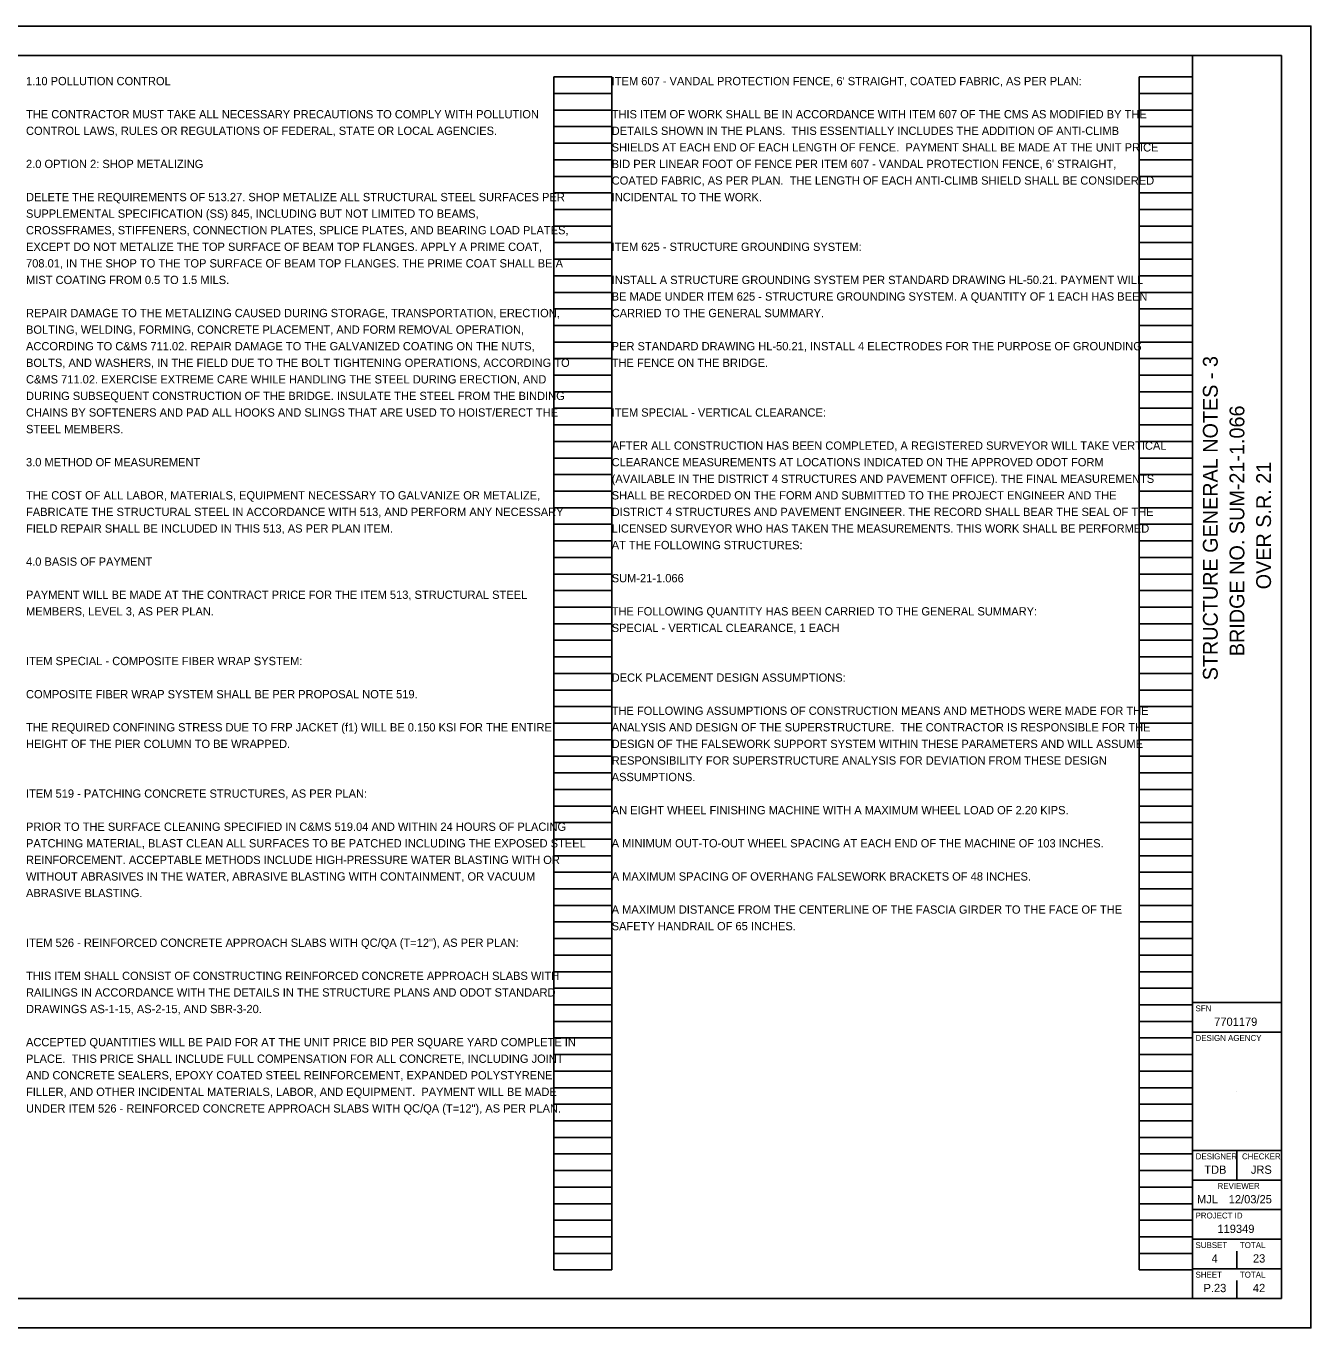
# Model space of a CAD drawing. Extents: x 0 to 34, y 0 to 22.
# Drawn here: x 12.29 to 34, y 0 to 22 of the extents above; entities that cross this region are included whole.
import ezdxf

# ---------------------------------------------------------------- set-up
doc = ezdxf.new("R2010")
doc.units = 0
for name, color, linetype in [('SH_Border', 7, 'Continuous'), ('SH_Cut_Line', 7, 'Continuous'), ('SH_Data', 7, 'Continuous'), ('SH_Text', 7, 'Continuous')]:
    doc.layers.add(name, color=color, linetype=linetype)

msp = doc.modelspace()

# ---------------------------------------------------------------- linework, layer by layer
at = {"layer": 'SH_Border'}
for p, q in [((32, 0.5), (32, 21.5)), ((32, 5.5), (33.5, 5.5)), ((32, 5), (33.5, 5)), ((32, 3), (33.5, 3)), ((32.75, 3), (32.75, 2.5)), ((32, 2.5), (33.5, 2.5)), ((32, 2), (33.5, 2)), ((32, 1.5), (33.5, 1.5)), ((32, 1), (33.5, 1))]:
    msp.add_line(p, q, dxfattribs=at)
msp.add_lwpolyline([(1.5, 21.5), (33.5, 21.5), (33.5, 0.5), (1.5, 0.5)], close=True, dxfattribs=at)
at = {"layer": 'SH_Cut_Line'}
msp.add_lwpolyline([(0, 0), (34, 0), (34, 22), (0, 22)], close=True, dxfattribs=at)
at = {"layer": 'SH_Data'}
for p, q in [((21.207, 0.98), (21.207, 21.14)), ((21.207, 21.14), (22.187, 21.14)), ((22.187, 0.98), (22.187, 21.14)), ((31.1, 0.98), (31.1, 21.14)), ((31.1, 21.14), (32, 21.14)), ((32, 0.98), (32, 21.14)), ((21.207, 20.86), (22.187, 20.86)), ((31.1, 20.86), (32, 20.86)), ((21.207, 20.58), (22.187, 20.58)), ((31.1, 20.58), (32, 20.58)), ((21.207, 20.3), (22.187, 20.3)), ((31.1, 20.3), (32, 20.3)), ((21.207, 20.02), (22.187, 20.02)), ((31.1, 20.02), (32, 20.02)), ((21.207, 19.74), (22.187, 19.74)), ((31.1, 19.74), (32, 19.74)), ((21.207, 19.46), (22.187, 19.46)), ((31.1, 19.46), (32, 19.46)), ((21.207, 19.18), (22.187, 19.18)), ((31.1, 19.18), (32, 19.18)), ((21.207, 18.9), (22.187, 18.9)), ((31.1, 18.9), (32, 18.9)), ((21.207, 18.62), (22.187, 18.62)), ((31.1, 18.62), (32, 18.62)), ((21.207, 18.34), (22.187, 18.34)), ((31.1, 18.34), (32, 18.34)), ((21.207, 18.06), (22.187, 18.06)), ((31.1, 18.06), (32, 18.06)), ((21.207, 17.78), (22.187, 17.78)), ((31.1, 17.78), (32, 17.78)), ((21.207, 17.5), (22.187, 17.5)), ((31.1, 17.5), (32, 17.5)), ((21.207, 17.22), (22.187, 17.22)), ((31.1, 17.22), (32, 17.22)), ((21.207, 16.94), (22.187, 16.94)), ((31.1, 16.94), (32, 16.94)), ((21.207, 16.66), (22.187, 16.66)), ((31.1, 16.66), (32, 16.66)), ((21.207, 16.38), (22.187, 16.38)), ((31.1, 16.38), (32, 16.38)), ((21.207, 16.1), (22.187, 16.1)), ((31.1, 16.1), (32, 16.1)), ((21.207, 15.82), (22.187, 15.82)), ((31.1, 15.82), (32, 15.82)), ((21.207, 15.54), (22.187, 15.54)), ((31.1, 15.54), (32, 15.54)), ((21.207, 15.26), (22.187, 15.26)), ((31.1, 15.26), (32, 15.26)), ((21.207, 14.98), (22.187, 14.98)), ((31.1, 14.98), (32, 14.98)), ((21.207, 14.7), (22.187, 14.7)), ((31.1, 14.7), (32, 14.7)), ((21.207, 14.42), (22.187, 14.42)), ((31.1, 14.42), (32, 14.42)), ((21.207, 14.14), (22.187, 14.14)), ((31.1, 14.14), (32, 14.14)), ((21.207, 13.86), (22.187, 13.86)), ((31.1, 13.86), (32, 13.86)), ((21.207, 13.58), (22.187, 13.58)), ((31.1, 13.58), (32, 13.58)), ((21.207, 13.3), (22.187, 13.3)), ((31.1, 13.3), (32, 13.3)), ((21.207, 13.02), (22.187, 13.02)), ((31.1, 13.02), (32, 13.02)), ((21.207, 12.74), (22.187, 12.74)), ((31.1, 12.74), (32, 12.74)), ((21.207, 12.46), (22.187, 12.46)), ((31.1, 12.46), (32, 12.46)), ((21.207, 12.18), (22.187, 12.18)), ((31.1, 12.18), (32, 12.18)), ((21.207, 11.9), (22.187, 11.9)), ((31.1, 11.9), (32, 11.9)), ((21.207, 11.62), (22.187, 11.62)), ((31.1, 11.62), (32, 11.62)), ((21.207, 11.34), (22.187, 11.34)), ((31.1, 11.34), (32, 11.34)), ((21.207, 11.06), (22.187, 11.06)), ((31.1, 11.06), (32, 11.06)), ((21.207, 10.78), (22.187, 10.78)), ((31.1, 10.78), (32, 10.78)), ((21.207, 10.5), (22.187, 10.5)), ((31.1, 10.5), (32, 10.5)), ((21.207, 10.22), (22.187, 10.22)), ((31.1, 10.22), (32, 10.22)), ((21.207, 9.94), (22.187, 9.94)), ((31.1, 9.94), (32, 9.94)), ((21.207, 9.66), (22.187, 9.66)), ((31.1, 9.66), (32, 9.66)), ((21.207, 9.38), (22.187, 9.38)), ((31.1, 9.38), (32, 9.38)), ((21.207, 9.1), (22.187, 9.1)), ((31.1, 9.1), (32, 9.1)), ((21.207, 8.82), (22.187, 8.82)), ((31.1, 8.82), (32, 8.82)), ((21.207, 8.54), (22.187, 8.54)), ((31.1, 8.54), (32, 8.54)), ((21.207, 8.26), (22.187, 8.26)), ((31.1, 8.26), (32, 8.26)), ((21.207, 7.98), (22.187, 7.98)), ((31.1, 7.98), (32, 7.98)), ((21.207, 7.7), (22.187, 7.7)), ((31.1, 7.7), (32, 7.7)), ((21.207, 7.42), (22.187, 7.42)), ((31.1, 7.42), (32, 7.42)), ((21.207, 7.14), (22.187, 7.14)), ((31.1, 7.14), (32, 7.14)), ((21.207, 6.86), (22.187, 6.86)), ((31.1, 6.86), (32, 6.86)), ((21.207, 6.58), (22.187, 6.58)), ((31.1, 6.58), (32, 6.58)), ((21.207, 6.3), (22.187, 6.3)), ((31.1, 6.3), (32, 6.3)), ((21.207, 6.02), (22.187, 6.02)), ((31.1, 6.02), (32, 6.02)), ((21.207, 5.74), (22.187, 5.74)), ((31.1, 5.74), (32, 5.74)), ((21.207, 5.46), (22.187, 5.46)), ((31.1, 5.46), (32, 5.46)), ((21.207, 5.18), (22.187, 5.18)), ((31.1, 5.18), (32, 5.18)), ((21.207, 4.9), (22.187, 4.9)), ((31.1, 4.9), (32, 4.9)), ((21.207, 4.62), (22.187, 4.62)), ((31.1, 4.62), (32, 4.62)), ((21.207, 4.34), (22.187, 4.34)), ((31.1, 4.34), (32, 4.34)), ((21.207, 4.06), (22.187, 4.06)), ((31.1, 4.06), (32, 4.06)), ((32.75, 4), (32.75, 4)), ((21.207, 3.78), (22.187, 3.78)), ((31.1, 3.78), (32, 3.78)), ((21.207, 3.5), (22.187, 3.5)), ((31.1, 3.5), (32, 3.5)), ((21.207, 3.22), (22.187, 3.22)), ((31.1, 3.22), (32, 3.22)), ((21.207, 2.94), (22.187, 2.94)), ((31.1, 2.94), (32, 2.94)), ((21.207, 2.66), (22.187, 2.66)), ((31.1, 2.66), (32, 2.66)), ((21.207, 2.38), (22.187, 2.38)), ((31.1, 2.38), (32, 2.38)), ((21.207, 2.1), (22.187, 2.1)), ((31.1, 2.1), (32, 2.1)), ((21.207, 1.82), (22.187, 1.82)), ((31.1, 1.82), (32, 1.82)), ((21.207, 1.54), (22.187, 1.54)), ((31.1, 1.54), (32, 1.54)), ((21.207, 1.26), (22.187, 1.26)), ((31.1, 1.26), (32, 1.26)), ((32.75, 1), (32.75, 1.3)), ((21.207, 0.98), (22.187, 0.98)), ((31.1, 0.98), (32, 0.98)), ((32.375, 0.675), (32.375, 0.675)), ((32.75, 0.5), (32.75, 0.8))]:
    msp.add_line(p, q, dxfattribs=at)

# ---------------------------------------------------------------- texts
for s, p in [('STRUCTURE GENERAL NOTES - 3', (32.425, 10.944)), ('BRIDGE NO. SUM-21-1.066', (32.875, 11.352)), ('OVER S.R. 21', (33.325, 12.482))]:
    msp.add_text(s, height=0.25, rotation=90, dxfattribs=at).set_placement(p)
for s, height, p in [('SFN', 0.1, (32.05, 5.35)), ('7701179', 0.14, (32.365, 5.105)), ('DESIGN AGENCY', 0.1, (32.05, 4.85)), ('DESIGNER', 0.1, (32.054, 2.85)), ('CHECKER', 0.1, (32.835, 2.85)), ('TDB', 0.14, (32.198, 2.605)), ('JRS', 0.14, (32.985, 2.605)), ('REVIEWER', 0.1, (32.422, 2.35)), ('MJL', 0.14, (32.075, 2.105)), ('12/03/25', 0.14, (32.611, 2.105)), ('PROJECT ID', 0.1, (32.05, 1.85)), ('119349', 0.14, (32.42, 1.605)), ('SUBSET', 0.1, (32.05, 1.35)), ('TOTAL', 0.1, (32.8, 1.35)), ('4', 0.14, (32.322, 1.105)), ('23', 0.14, (33.02, 1.105)), ('SHEET', 0.1, (32.05, 0.85)), ('TOTAL', 0.1, (32.8, 0.85)), ('P.23', 0.14, (32.185, 0.605)), ('42', 0.14, (33.019, 0.605))]:
    msp.add_text(s, height=height, dxfattribs=at).set_placement(p)
at = {"layer": 'SH_Text'}
for s, p in [('1.10 POLLUTION CONTROL', (12.293, 21)), ("ITEM 607 - VANDAL PROTECTION FENCE, 6' STRAIGHT, COATED FABRIC, AS PER PLAN:", (22.187, 21)), ('THE CONTRACTOR MUST TAKE ALL NECESSARY PRECAUTIONS TO COMPLY WITH POLLUTION ', (12.293, 20.44)), ('THIS ITEM OF WORK SHALL BE IN ACCORDANCE WITH ITEM 607 OF THE CMS AS MODIFIED BY THE ', (22.187, 20.44)), ('CONTROL LAWS, RULES OR REGULATIONS OF FEDERAL, STATE OR LOCAL AGENCIES.', (12.293, 20.16)), ('DETAILS SHOWN IN THE PLANS.  THIS ESSENTIALLY INCLUDES THE ADDITION OF ANTI-CLIMB ', (22.187, 20.16)), ('SHIELDS AT EACH END OF EACH LENGTH OF FENCE.  PAYMENT SHALL BE MADE AT THE UNIT PRICE ', (22.187, 19.88)), ('2.0 OPTION 2: SHOP METALIZING', (12.293, 19.6)), ("BID PER LINEAR FOOT OF FENCE PER ITEM 607 - VANDAL PROTECTION FENCE, 6' STRAIGHT, ", (22.187, 19.6)), ('COATED FABRIC, AS PER PLAN.  THE LENGTH OF EACH ANTI-CLIMB SHIELD SHALL BE CONSIDERED ', (22.187, 19.32)), ('DELETE THE REQUIREMENTS OF 513.27. SHOP METALIZE ALL STRUCTURAL STEEL SURFACES PER ', (12.293, 19.04)), ('INCIDENTAL TO THE WORK.', (22.187, 19.04)), ('SUPPLEMENTAL SPECIFICATION (SS) 845, INCLUDING BUT NOT LIMITED TO BEAMS,', (12.293, 18.76)), ('CROSSFRAMES, STIFFENERS, CONNECTION PLATES, SPLICE PLATES, AND BEARING LOAD PLATES, ', (12.293, 18.48)), ('EXCEPT DO NOT METALIZE THE TOP SURFACE OF BEAM TOP FLANGES. APPLY A PRIME COAT, ', (12.293, 18.2)), ('ITEM 625 - STRUCTURE GROUNDING SYSTEM:', (22.187, 18.2)), ('708.01, IN THE SHOP TO THE TOP SURFACE OF BEAM TOP FLANGES. THE PRIME COAT SHALL BE A ', (12.293, 17.92)), ('MIST COATING FROM 0.5 TO 1.5 MILS.', (12.293, 17.64)), ('INSTALL A STRUCTURE GROUNDING SYSTEM PER STANDARD DRAWING HL-50.21. PAYMENT WILL ', (22.187, 17.64)), ('BE MADE UNDER ITEM 625 - STRUCTURE GROUNDING SYSTEM. A QUANTITY OF 1 EACH HAS BEEN ', (22.187, 17.36)), ('REPAIR DAMAGE TO THE METALIZING CAUSED DURING STORAGE, TRANSPORTATION, ERECTION, ', (12.293, 17.08)), ('CARRIED TO THE GENERAL SUMMARY.', (22.187, 17.08)), ('BOLTING, WELDING, FORMING, CONCRETE PLACEMENT, AND FORM REMOVAL OPERATION, ', (12.293, 16.8)), ('ACCORDING TO C&MS 711.02. REPAIR DAMAGE TO THE GALVANIZED COATING ON THE NUTS, ', (12.293, 16.52)), ('PER STANDARD DRAWING HL-50.21, INSTALL 4 ELECTRODES FOR THE PURPOSE OF GROUNDING ', (22.187, 16.52)), ('BOLTS, AND WASHERS, IN THE FIELD DUE TO THE BOLT TIGHTENING OPERATIONS, ACCORDING TO ', (12.293, 16.24)), ('THE FENCE ON THE BRIDGE.', (22.187, 16.24)), ('C&MS 711.02. EXERCISE EXTREME CARE WHILE HANDLING THE STEEL DURING ERECTION, AND ', (12.293, 15.96)), ('DURING SUBSEQUENT CONSTRUCTION OF THE BRIDGE. INSULATE THE STEEL FROM THE BINDING ', (12.293, 15.68)), ('CHAINS BY SOFTENERS AND PAD ALL HOOKS AND SLINGS THAT ARE USED TO HOIST/ERECT THE ', (12.293, 15.4)), ('ITEM SPECIAL - VERTICAL CLEARANCE:', (22.187, 15.4)), ('STEEL MEMBERS.', (12.293, 15.12)), ('AFTER ALL CONSTRUCTION HAS BEEN COMPLETED, A REGISTERED SURVEYOR WILL TAKE VERTICAL ', (22.187, 14.84)), ('3.0 METHOD OF MEASUREMENT', (12.293, 14.56)), ('CLEARANCE MEASUREMENTS AT LOCATIONS INDICATED ON THE APPROVED ODOT FORM ', (22.187, 14.56)), ('(AVAILABLE IN THE DISTRICT 4 STRUCTURES AND PAVEMENT OFFICE). THE FINAL MEASUREMENTS ', (22.187, 14.28)), ('THE COST OF ALL LABOR, MATERIALS, EQUIPMENT NECESSARY TO GALVANIZE OR METALIZE, ', (12.293, 14)), ('SHALL BE RECORDED ON THE FORM AND SUBMITTED TO THE PROJECT ENGINEER AND THE ', (22.187, 14)), ('FABRICATE THE STRUCTURAL STEEL IN ACCORDANCE WITH 513, AND PERFORM ANY NECESSARY ', (12.293, 13.72)), ('DISTRICT 4 STRUCTURES AND PAVEMENT ENGINEER. THE RECORD SHALL BEAR THE SEAL OF THE ', (22.187, 13.72)), ('FIELD REPAIR SHALL BE INCLUDED IN THIS 513, AS PER PLAN ITEM.', (12.293, 13.44)), ('LICENSED SURVEYOR WHO HAS TAKEN THE MEASUREMENTS. THIS WORK SHALL BE PERFORMED ', (22.187, 13.44)), ('AT THE FOLLOWING STRUCTURES: ', (22.187, 13.16)), ('4.0 BASIS OF PAYMENT', (12.293, 12.88)), ('SUM-21-1.066', (22.187, 12.6)), ('PAYMENT WILL BE MADE AT THE CONTRACT PRICE FOR THE ITEM 513, STRUCTURAL STEEL ', (12.293, 12.32)), ('MEMBERS, LEVEL 3, AS PER PLAN.', (12.293, 12.04)), ('THE FOLLOWING QUANTITY HAS BEEN CARRIED TO THE GENERAL SUMMARY: ', (22.187, 12.04)), ('SPECIAL - VERTICAL CLEARANCE, 1 EACH', (22.187, 11.76)), ('ITEM SPECIAL - COMPOSITE FIBER WRAP SYSTEM:', (12.293, 11.2)), ('DECK PLACEMENT DESIGN ASSUMPTIONS:', (22.187, 10.92)), ('COMPOSITE FIBER WRAP SYSTEM SHALL BE PER PROPOSAL NOTE 519.', (12.293, 10.64)), ('THE FOLLOWING ASSUMPTIONS OF CONSTRUCTION MEANS AND METHODS WERE MADE FOR THE ', (22.187, 10.36)), ('THE REQUIRED CONFINING STRESS DUE TO FRP JACKET (f1) WILL BE 0.150 KSI FOR THE ENTIRE ', (12.293, 10.08)), ('ANALYSIS AND DESIGN OF THE SUPERSTRUCTURE.  THE CONTRACTOR IS RESPONSIBLE FOR THE ', (22.187, 10.08)), ('HEIGHT OF THE PIER COLUMN TO BE WRAPPED.', (12.293, 9.8)), ('DESIGN OF THE FALSEWORK SUPPORT SYSTEM WITHIN THESE PARAMETERS AND WILL ASSUME ', (22.187, 9.8)), ('RESPONSIBILITY FOR SUPERSTRUCTURE ANALYSIS FOR DEVIATION FROM THESE DESIGN ', (22.187, 9.52)), ('ASSUMPTIONS.', (22.187, 9.24)), ('ITEM 519 - PATCHING CONCRETE STRUCTURES, AS PER PLAN:', (12.293, 8.96)), ('AN EIGHT WHEEL FINISHING MACHINE WITH A MAXIMUM WHEEL LOAD OF 2.20 KIPS.', (22.187, 8.68)), ('PRIOR TO THE SURFACE CLEANING SPECIFIED IN C&MS 519.04 AND WITHIN 24 HOURS OF PLACING ', (12.293, 8.4)), ('PATCHING MATERIAL, BLAST CLEAN ALL SURFACES TO BE PATCHED INCLUDING THE EXPOSED STEEL ', (12.293, 8.12)), ('A MINIMUM OUT-TO-OUT WHEEL SPACING AT EACH END OF THE MACHINE OF 103 INCHES.', (22.187, 8.12)), ('REINFORCEMENT. ACCEPTABLE METHODS INCLUDE HIGH-PRESSURE WATER BLASTING WITH OR ', (12.293, 7.84)), ('WITHOUT ABRASIVES IN THE WATER, ABRASIVE BLASTING WITH CONTAINMENT, OR VACUUM ', (12.293, 7.56)), ('A MAXIMUM SPACING OF OVERHANG FALSEWORK BRACKETS OF 48 INCHES.', (22.187, 7.56)), ('ABRASIVE BLASTING.', (12.293, 7.28)), ('A MAXIMUM DISTANCE FROM THE CENTERLINE OF THE FASCIA GIRDER TO THE FACE OF THE ', (22.187, 7)), ('SAFETY HANDRAIL OF 65 INCHES.', (22.187, 6.72)), ('ITEM 526 - REINFORCED CONCRETE APPROACH SLABS WITH QC/QA (T=12"), AS PER PLAN:', (12.293, 6.44)), ('THIS ITEM SHALL CONSIST OF CONSTRUCTING REINFORCED CONCRETE APPROACH SLABS WITH ', (12.293, 5.88)), ('RAILINGS IN ACCORDANCE WITH THE DETAILS IN THE STRUCTURE PLANS AND ODOT STANDARD ', (12.293, 5.6)), ('DRAWINGS AS-1-15, AS-2-15, AND SBR-3-20.', (12.293, 5.32)), ('ACCEPTED QUANTITIES WILL BE PAID FOR AT THE UNIT PRICE BID PER SQUARE YARD COMPLETE IN ', (12.293, 4.76)), ('PLACE.  THIS PRICE SHALL INCLUDE FULL COMPENSATION FOR ALL CONCRETE, INCLUDING JOINT ', (12.293, 4.48)), ('AND CONCRETE SEALERS, EPOXY COATED STEEL REINFORCEMENT, EXPANDED POLYSTYRENE ', (12.293, 4.2)), ('FILLER, AND OTHER INCIDENTAL MATERIALS, LABOR, AND EQUIPMENT.  PAYMENT WILL BE MADE ', (12.293, 3.92)), ('UNDER ITEM 526 - REINFORCED CONCRETE APPROACH SLABS WITH QC/QA (T=12"), AS PER PLAN.', (12.293, 3.64))]:
    msp.add_text(s, height=0.14, dxfattribs=at).set_placement(p)

doc.saveas('drawing.dxf')
